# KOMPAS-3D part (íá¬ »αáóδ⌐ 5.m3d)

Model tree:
1. Эскиз:1
2. Операция выдавливания:1
     Расстояние 1 = 10
3. Эскиз:2
4. Вырезать элемент выдавливания:1
     Расстояние 1 = 34.8
5. Скругление:1
     Радиус = 1
6. Скругление:2
     Радиус = 2
7. Эскиз:3
8. Вырезать элемент выдавливания:2
     Расстояние 1 = 0.2
9. Скругление:3
     Радиус = 0.1
10. Эскиз:4
11. Операция выдавливания:2
     Расстояние 1 = 0.5; Расстояние 2 = 4.9
12. Скругление:4
     Радиус = 0.2
13. Эскиз:5
14. Операция выдавливания:3
     Расстояние 1 = 0.5; Расстояние 2 = 4.9
15. Эскиз:6
16. Операция выдавливания:4
     Расстояние 1 = 1; Расстояние 2 = 4.9
17. Эскиз:7
18. Операция выдавливания:5
     Расстояние 1 = 0.3; Расстояние 2 = 4.9
19. Массив по концентрической сетке:1  (with: Операция выдавливания:5)  (labels: Экземпляр ( 1, 1 ); Экземпляр ( 1, 2 ); Экземпляр ( 1, 3 ))
     N 2 = 3; Шаг 2 = 360; Номер 2 = 1

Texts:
  бак правый 5
  Сплав АЛ8  ГОСТ 1583-93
